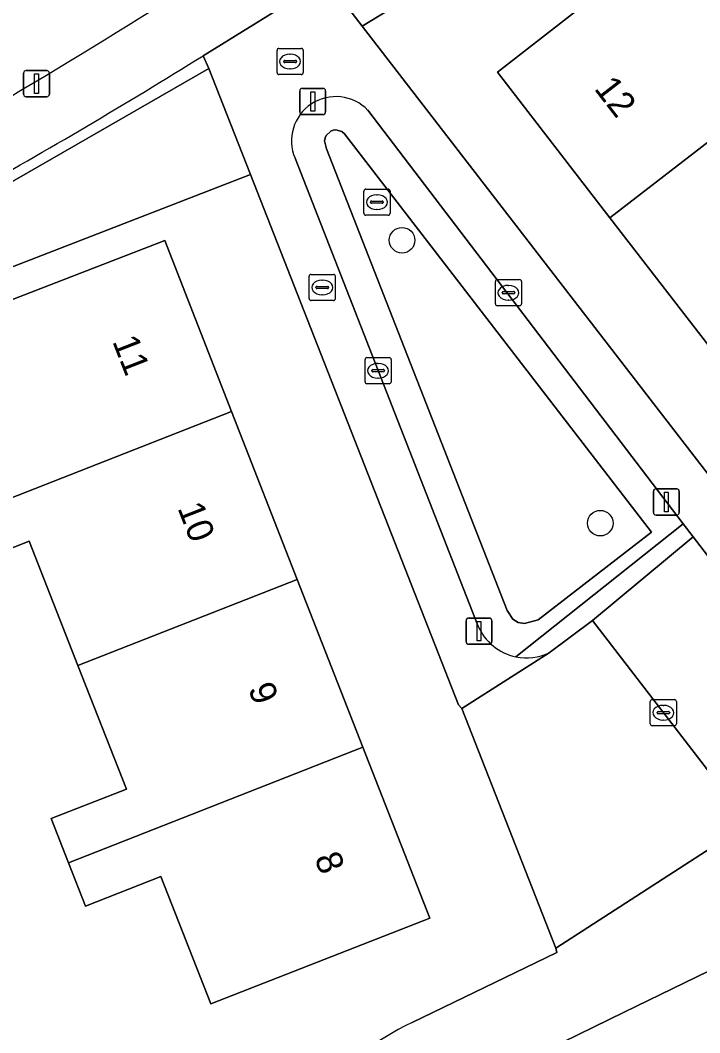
# Model space of a CAD drawing. Extents: x 162661 to 163484, y 380247 to 381230.
# Drawn here: x 163145.52 to 163171.51, y 381014.16 to 381052.89 of the extents above; entities that cross this region are included whole.
import ezdxf

# ---------------------------------------------------------------- set-up
doc = ezdxf.new("R2010")
doc.units = 0
for name, color, linetype in [('IMGEO_Boom', 7, 'Continuous'), ('IMGEO_Brandkraan', 7, 'Continuous'), ('IMGEO_Erf', 7, 'Continuous'), ('IMGEO_Groenvoorziening', 7, 'Continuous'), ('IMGEO_Kolk', 7, 'Continuous'), ('IMGEO_Lichtmast', 7, 'Continuous'), ('IMGEO_Loofbos', 7, 'Continuous'), ('IMGEO_Pand', 7, 'Continuous'), ('IMGEO_Pand_nummerreeks', 7, 'Continuous'), ('IMGEO_Parkeervlak_open', 7, 'Continuous'), ('IMGEO_Rijbaan_lokaal_open', 7, 'Continuous'), ('IMGEO_Rioolput', 7, 'Continuous'), ('IMGEO_Voetpad_open', 7, 'Continuous')]:
    doc.layers.add(name, color=color, linetype=linetype)

msp = doc.modelspace()

# ---------------------------------------------------------------- linework, layer by layer
at = {"layer": 'IMGEO_Boom'}
for centre in [(163160.123, 381044.477), (163167.702, 381033.654)]:
    msp.add_circle(centre, 0.489, dxfattribs=at)
at = {"layer": 'IMGEO_Brandkraan'}
for p, q in [((163156.57, 381042.245), (163156.57, 381043.097)), ((163156.645, 381043.171), (163157.497, 381043.171)), ((163157.571, 381043.097), (163157.571, 381042.245)), ((163156.872, 381042.714), (163157.27, 381042.714)), ((163157.058, 381042.951), (163157.083, 381042.951)), ((163156.829, 381042.665), (163156.829, 381042.677)), ((163157.267, 381042.628), (163156.869, 381042.628)), ((163157.081, 381042.391), (163157.056, 381042.391)), ((163157.313, 381042.677), (163157.313, 381042.665)), ((163157.497, 381042.171), (163156.645, 381042.171))]:
    msp.add_line(p, q, dxfattribs=at)
for points in [[(163156.57, 381042.245), (163156.57, 381043.097)], [(163156.645, 381043.171), (163157.497, 381043.171)], [(163157.571, 381043.097), (163157.571, 381042.245)], [(163157.497, 381042.171), (163156.645, 381042.171)]]:
    msp.add_lwpolyline(points, dxfattribs=at)
for centre, radius, start, end in [((163156.647, 381043.095), 0.0765, 91.552, 178.448), ((163156.647, 381043.095), 0.0765, 91.552, 178.448), ((163157.495, 381043.095), 0.0765, 1.552, 88.448), ((163157.495, 381043.095), 0.0765, 1.552, 88.448), ((163156.869, 381042.674), 0.0403, 85.8775, 175.7526), ((163157.274, 381042.676), 0.0386, 1.7309, 96.639), ((163156.866, 381042.664), 0.0366, 178.938, 274.7102), ((163157.27, 381042.671), 0.043, 264.8664, 352.4533), ((163156.647, 381042.247), 0.0765, 181.552, 268.448), ((163156.647, 381042.247), 0.0765, 181.552, 268.448), ((163157.495, 381042.247), 0.0765, 271.552, 358.448), ((163157.495, 381042.247), 0.0765, 271.552, 358.448)]:
    msp.add_arc(centre, radius, start, end, dxfattribs=at)
for centre, major_axis, ratio, start_param, end_param in [((163157.057, 381042.671), (-0.387, 0.002), 0.722429, 4.712389, 7.853982), ((163157.082, 381042.671), (-0.39, 0.002), 0.717154, 1.570796, 4.712389)]:
    msp.add_ellipse(centre, major_axis=major_axis, ratio=ratio, start_param=start_param, end_param=end_param, dxfattribs=at)
at = {"layer": 'IMGEO_Erf'}
for points in [[(163183.983, 381058.045), (163198.909, 381037.268), (163207.172, 381043.323), (163215.696, 381049.583), (163215.608, 381049.723), (163210.472, 381058.155), (163197.39, 381079.623), (163187.607, 381072.029), (163175.603, 381063.541), (163168.423, 381058.662), (163158.593, 381052.674), (163180.067, 381024.856)], [(163162.414, 381026.565), (163162.279, 381026.698), (163154.328, 381046.987), (163144.896, 381043.328), (163143.928, 381045.981), (163137.766, 381042.44), (163133.585, 381040.037), (163133.484, 381038.184), (163132.855, 381030.173), (163133.892, 381030.091), (163132.494, 381012.197), (163152.72, 381007.872), (163152.681, 381007.77), (163154.245, 381007.436), (163154.323, 381007.677)], [(163160.511, 381014.551), (163166.037, 381017.229), (163166.001, 381017.389), (163162.414, 381026.565)]]:
    msp.add_lwpolyline(points, dxfattribs=at)
for points in [[(163174.064, 381052.219), (163176.518, 381054.118), (163177.61, 381052.709), (163178.706, 381051.294), (163176.245, 381049.39), (163179.376, 381045.345), (163182.493, 381041.318), (163184.948, 381043.218), (163186.063, 381041.778), (163187.153, 381040.369), (163184.694, 381038.464), (163187.904, 381034.319), (163184.319, 381031.553), (163185.906, 381029.496), (163182.75, 381027.061), (163181.163, 381029.118), (163180.804, 381028.841), (163176.51, 381034.403), (163172.286, 381039.873), (163168.065, 381045.341), (163163.768, 381050.906), (163170.824, 381056.405)], [(163147.725, 381028.21), (163145.86, 381032.964), (163142.978, 381031.833), (163142.322, 381033.501), (163141.663, 381035.179), (163144.544, 381036.31), (163142.625, 381041.199), (163145.295, 381042.235), (163151.049, 381044.467), (163153.604, 381037.927), (163156.115, 381031.501), (163158.624, 381025.077), (163161.179, 381018.538), (163152.811, 381015.257), (163150.896, 381020.137), (163148.014, 381019.006), (163147.364, 381020.659), (163146.699, 381022.352), (163149.58, 381023.482)]]:
    msp.add_lwpolyline(points, close=True, dxfattribs=at)
msp.add_arc((163165.964, 381003.42), 12.395, 116.0996, 159.913, dxfattribs=at)
at = {"layer": 'IMGEO_Groenvoorziening'}
for points in [[(163157.958, 381053.496), (163158.593, 381052.674), (163168.423, 381058.662), (163175.603, 381063.541), (163187.607, 381072.029), (163197.39, 381079.623), (163196.99, 381080.281), (163177.8, 381066.44)], [(163154.328, 381046.987), (163153.268, 381049.69), (163152.737, 381051.044), (163143.928, 381045.981), (163144.896, 381043.328)], [(163164.8, 381029.811), (163165.325, 381029.957), (163169.666, 381033.313), (163157.928, 381048.553), (163157.821, 381048.635), (163157.59, 381048.703), (163157.489, 381048.695), (163157.395, 381048.655), (163157.22, 381048.488), (163157.177, 381048.397), (163157.162, 381048.281), (163157.228, 381047.979), (163164.143, 381030.309), (163164.353, 381029.985), (163164.561, 381029.85)], [(163157.228, 381047.979), (163157.162, 381048.281), (163157.177, 381048.397), (163157.22, 381048.488), (163157.395, 381048.655), (163157.489, 381048.695), (163157.59, 381048.703), (163157.821, 381048.635), (163157.928, 381048.553), (163169.666, 381033.313), (163165.325, 381029.957), (163164.8, 381029.811), (163164.561, 381029.85), (163164.353, 381029.985), (163164.143, 381030.309)]]:
    msp.add_lwpolyline(points, close=True, dxfattribs=at)
for points in [[(163152.737, 381051.044), (163152.52, 381051.539)], [(163137.038, 381042.612), (163137.766, 381042.44), (163143.928, 381045.981), (163152.737, 381051.044)], [(163164.477, 381028.541), (163170.874, 381033.624), (163158.817, 381049.448)], [(163156.029, 381047.613), (163163.024, 381029.737)]]:
    msp.add_lwpolyline(points, dxfattribs=at)
for centre, radius, start, end in [((163030.104, 381248.524), 231.924, 299.2798, 301.85889), ((163157.591, 381048.276), 1.696, 43.7034, 203.0007), ((163164.885, 381030.518), 2.019, 202.7562, 258.3266)]:
    msp.add_arc(centre, radius, start, end, dxfattribs=at)
at = {"layer": 'IMGEO_Kolk'}
for p, q in [((163155.341, 381050.891), (163155.341, 381051.743)), ((163155.416, 381051.817), (163156.268, 381051.817)), ((163156.342, 381051.743), (163156.342, 381050.891)), ((163155.6, 381051.311), (163155.6, 381051.323)), ((163156.038, 381051.274), (163155.64, 381051.274)), ((163155.643, 381051.36), (163156.041, 381051.36)), ((163155.829, 381051.597), (163155.854, 381051.597)), ((163156.084, 381051.323), (163156.084, 381051.311)), ((163155.852, 381051.037), (163155.827, 381051.037)), ((163156.268, 381050.817), (163155.416, 381050.817)), ((163163.691, 381042.044), (163163.691, 381042.896)), ((163163.766, 381042.97), (163164.618, 381042.97)), ((163164.179, 381042.75), (163164.204, 381042.75)), ((163164.692, 381042.896), (163164.692, 381042.044)), ((163163.95, 381042.464), (163163.95, 381042.476)), ((163164.388, 381042.427), (163163.99, 381042.427)), ((163163.993, 381042.513), (163164.391, 381042.513)), ((163164.434, 381042.476), (163164.434, 381042.464)), ((163164.618, 381041.97), (163163.766, 381041.97)), ((163164.202, 381042.19), (163164.177, 381042.19)), ((163158.706, 381039.06), (163158.706, 381039.912)), ((163158.781, 381039.986), (163159.633, 381039.986)), ((163159.194, 381039.766), (163159.219, 381039.766)), ((163159.707, 381039.912), (163159.707, 381039.06)), ((163158.965, 381039.48), (163158.965, 381039.492)), ((163159.403, 381039.443), (163159.005, 381039.443)), ((163159.008, 381039.529), (163159.406, 381039.529)), ((163159.449, 381039.492), (163159.449, 381039.48)), ((163159.633, 381038.986), (163158.781, 381038.986)), ((163159.217, 381039.206), (163159.192, 381039.206)), ((163169.614, 381025.976), (163169.614, 381026.828)), ((163169.689, 381026.902), (163170.541, 381026.902)), ((163170.615, 381026.828), (163170.615, 381025.976)), ((163169.916, 381026.445), (163170.314, 381026.445)), ((163170.102, 381026.682), (163170.127, 381026.682)), ((163169.873, 381026.396), (163169.873, 381026.408)), ((163170.311, 381026.359), (163169.913, 381026.359)), ((163170.125, 381026.122), (163170.1, 381026.122)), ((163170.357, 381026.408), (163170.357, 381026.396)), ((163170.541, 381025.902), (163169.689, 381025.902))]:
    msp.add_line(p, q, dxfattribs=at)
for points in [[(163155.341, 381050.891), (163155.341, 381051.743)], [(163155.416, 381051.817), (163156.268, 381051.817)], [(163156.342, 381051.743), (163156.342, 381050.891)], [(163156.268, 381050.817), (163155.416, 381050.817)], [(163163.691, 381042.044), (163163.691, 381042.896)], [(163163.766, 381042.97), (163164.618, 381042.97)], [(163164.692, 381042.896), (163164.692, 381042.044)], [(163164.618, 381041.97), (163163.766, 381041.97)], [(163158.706, 381039.06), (163158.706, 381039.912)], [(163158.781, 381039.986), (163159.633, 381039.986)], [(163159.707, 381039.912), (163159.707, 381039.06)], [(163159.633, 381038.986), (163158.781, 381038.986)], [(163169.614, 381025.976), (163169.614, 381026.828)], [(163169.689, 381026.902), (163170.541, 381026.902)], [(163170.615, 381026.828), (163170.615, 381025.976)], [(163170.541, 381025.902), (163169.689, 381025.902)]]:
    msp.add_lwpolyline(points, dxfattribs=at)
for centre, radius, start, end in [((163155.418, 381051.741), 0.0765, 91.552, 178.448), ((163155.418, 381051.741), 0.0765, 91.552, 178.448), ((163156.266, 381051.741), 0.0765, 1.552, 88.448), ((163156.266, 381051.741), 0.0765, 1.552, 88.448), ((163155.64, 381051.32), 0.0403, 85.8775, 175.7526), ((163155.637, 381051.31), 0.0366, 178.938, 274.7102), ((163156.041, 381051.317), 0.043, 264.8664, 352.4533), ((163156.045, 381051.322), 0.0386, 1.7309, 96.639), ((163155.418, 381050.893), 0.0765, 181.552, 268.448), ((163155.418, 381050.893), 0.0765, 181.552, 268.448), ((163156.266, 381050.893), 0.0765, 271.552, 358.448), ((163156.266, 381050.893), 0.0765, 271.552, 358.448), ((163163.768, 381042.894), 0.0765, 91.552, 178.448), ((163163.768, 381042.894), 0.0765, 91.552, 178.448), ((163164.616, 381042.894), 0.0765, 1.552, 88.448), ((163164.616, 381042.894), 0.0765, 1.552, 88.448), ((163163.99, 381042.473), 0.0403, 85.8775, 175.7526), ((163163.987, 381042.463), 0.0366, 178.938, 274.7102), ((163164.391, 381042.47), 0.043, 264.8664, 352.4533), ((163164.395, 381042.475), 0.0386, 1.7309, 96.639), ((163163.768, 381042.046), 0.0765, 181.552, 268.448), ((163163.768, 381042.046), 0.0765, 181.552, 268.448), ((163164.616, 381042.046), 0.0765, 271.552, 358.448), ((163164.616, 381042.046), 0.0765, 271.552, 358.448), ((163158.783, 381039.91), 0.0765, 91.552, 178.448), ((163158.783, 381039.91), 0.0765, 91.552, 178.448), ((163159.631, 381039.91), 0.0765, 1.552, 88.448), ((163159.631, 381039.91), 0.0765, 1.552, 88.448), ((163159.005, 381039.489), 0.0403, 85.8775, 175.7526), ((163159.002, 381039.479), 0.0366, 178.938, 274.7102), ((163159.406, 381039.486), 0.043, 264.8664, 352.4533), ((163159.41, 381039.491), 0.0386, 1.7309, 96.639), ((163158.783, 381039.062), 0.0765, 181.552, 268.448), ((163158.783, 381039.062), 0.0765, 181.552, 268.448), ((163159.631, 381039.062), 0.0765, 271.552, 358.448), ((163159.631, 381039.062), 0.0765, 271.552, 358.448), ((163169.691, 381026.826), 0.0765, 91.552, 178.448), ((163169.691, 381026.826), 0.0765, 91.552, 178.448), ((163170.539, 381026.826), 0.0765, 1.552, 88.448), ((163170.539, 381026.826), 0.0765, 1.552, 88.448), ((163169.913, 381026.405), 0.0403, 85.8775, 175.7526), ((163170.318, 381026.407), 0.0386, 1.7309, 96.639), ((163169.91, 381026.395), 0.0366, 178.938, 274.7102), ((163170.314, 381026.402), 0.043, 264.8664, 352.4533), ((163169.691, 381025.978), 0.0765, 181.552, 268.448), ((163169.691, 381025.978), 0.0765, 181.552, 268.448), ((163170.539, 381025.978), 0.0765, 271.552, 358.448), ((163170.539, 381025.978), 0.0765, 271.552, 358.448)]:
    msp.add_arc(centre, radius, start, end, dxfattribs=at)
for centre, major_axis, ratio, start_param, end_param in [((163155.828, 381051.317), (-0.387, 0.002), 0.722429, 4.712389, 7.853982), ((163155.853, 381051.317), (-0.39, 0.002), 0.717154, 1.570796, 4.712389), ((163164.178, 381042.47), (-0.387, 0.002), 0.722429, 4.712389, 7.853982), ((163164.203, 381042.47), (-0.39, 0.002), 0.717154, 1.570796, 4.712389), ((163159.193, 381039.486), (-0.387, 0.002), 0.722429, 4.712389, 7.853982), ((163159.218, 381039.486), (-0.39, 0.002), 0.717154, 1.570796, 4.712389), ((163170.101, 381026.402), (-0.387, 0.002), 0.722429, 4.712389, 7.853982), ((163170.126, 381026.402), (-0.39, 0.002), 0.717154, 1.570796, 4.712389)]:
    msp.add_ellipse(centre, major_axis=major_axis, ratio=ratio, start_param=start_param, end_param=end_param, dxfattribs=at)
at = {"layer": 'IMGEO_Lichtmast'}
for p, q in [((163145.646, 381050.069), (163145.646, 381050.869)), ((163145.646, 381050.869), (163145.646, 381050.069)), ((163145.746, 381050.969), (163146.536, 381050.969)), ((163146.536, 381050.969), (163145.746, 381050.969)), ((163146.636, 381050.869), (163146.636, 381050.069)), ((163146.636, 381050.069), (163146.636, 381050.869)), ((163156.211, 381049.387), (163156.211, 381050.187)), ((163156.211, 381050.187), (163156.211, 381049.387)), ((163156.311, 381050.287), (163157.101, 381050.287)), ((163157.101, 381050.287), (163156.311, 381050.287)), ((163157.201, 381050.187), (163157.201, 381049.387)), ((163157.201, 381049.387), (163157.201, 381050.187)), ((163146.536, 381049.969), (163145.746, 381049.969)), ((163145.746, 381049.969), (163146.536, 381049.969)), ((163157.101, 381049.287), (163156.311, 381049.287)), ((163156.311, 381049.287), (163157.101, 381049.287)), ((163169.835, 381034.965), (163170.625, 381034.965)), ((163170.625, 381034.965), (163169.835, 381034.965)), ((163169.735, 381034.065), (163169.735, 381034.865)), ((163169.735, 381034.865), (163169.735, 381034.065)), ((163170.725, 381034.865), (163170.725, 381034.065)), ((163170.725, 381034.065), (163170.725, 381034.865)), ((163170.625, 381033.965), (163169.835, 381033.965)), ((163169.835, 381033.965), (163170.625, 381033.965)), ((163162.571, 381029.122), (163162.571, 381029.922)), ((163162.571, 381029.922), (163162.571, 381029.122)), ((163162.671, 381030.022), (163163.461, 381030.022)), ((163163.461, 381030.022), (163162.671, 381030.022)), ((163163.561, 381029.922), (163163.561, 381029.122)), ((163163.561, 381029.122), (163163.561, 381029.922)), ((163163.461, 381029.022), (163162.671, 381029.022)), ((163162.671, 381029.022), (163163.461, 381029.022))]:
    msp.add_line(p, q, dxfattribs=at)
for points in [[(163146.066, 381050.844), (163146.216, 381050.844), (163146.216, 381050.094), (163146.066, 381050.094), (163146.066, 381050.844)], [(163156.631, 381050.162), (163156.781, 381050.162), (163156.781, 381049.412), (163156.631, 381049.412), (163156.631, 381050.162)], [(163170.155, 381034.84), (163170.305, 381034.84), (163170.305, 381034.09), (163170.155, 381034.09), (163170.155, 381034.84)], [(163162.991, 381029.897), (163163.141, 381029.897), (163163.141, 381029.147), (163162.991, 381029.147), (163162.991, 381029.897)]]:
    msp.add_lwpolyline(points, dxfattribs=at)
for centre, start, end in [((163145.746, 381050.869), 90, 180), ((163145.746, 381050.869), 90, 180), ((163146.536, 381050.869), 0, 90), ((163146.536, 381050.869), 360, 90), ((163145.746, 381050.069), 180, 270), ((163145.746, 381050.069), 180, 270), ((163146.536, 381050.069), 270, 0), ((163146.536, 381050.069), 270, 0), ((163156.311, 381050.187), 90, 180), ((163156.311, 381050.187), 90, 180), ((163157.101, 381050.187), 0, 90), ((163157.101, 381050.187), 360, 90), ((163156.311, 381049.387), 180, 270), ((163156.311, 381049.387), 180, 270), ((163157.101, 381049.387), 270, 0), ((163157.101, 381049.387), 270, 0), ((163169.835, 381034.865), 90, 180), ((163169.835, 381034.865), 90, 180), ((163170.625, 381034.865), 0, 90), ((163170.625, 381034.865), 360, 90), ((163169.835, 381034.065), 180, 270), ((163169.835, 381034.065), 180, 270), ((163170.625, 381034.065), 270, 0), ((163170.625, 381034.065), 270, 0), ((163162.671, 381029.922), 90, 180), ((163162.671, 381029.922), 90, 180), ((163163.461, 381029.922), 0, 90), ((163163.461, 381029.922), 360, 90), ((163162.671, 381029.122), 180, 270), ((163162.671, 381029.122), 180, 270), ((163163.461, 381029.122), 270, 0), ((163163.461, 381029.122), 270, 0)]:
    msp.add_arc(centre, 0.1, start, end, dxfattribs=at)
at = {"layer": 'IMGEO_Loofbos'}
msp.add_arc((163001.958, 381290.973), 280.328, 298.74373, 302.22792, dxfattribs=at)
at = {"layer": 'IMGEO_Pand'}
for points in [[(163168.065, 381045.341), (163177.61, 381052.709), (163176.518, 381054.118), (163174.064, 381052.219), (163170.824, 381056.405), (163163.768, 381050.906)], [(163168.065, 381045.341), (163172.286, 381039.873), (163179.376, 381045.345), (163176.245, 381049.39), (163178.706, 381051.294), (163177.61, 381052.709)], [(163151.049, 381044.467), (163145.295, 381042.235), (163142.625, 381041.199), (163144.544, 381036.31), (163141.663, 381035.179), (163142.322, 381033.501), (163153.604, 381037.927)], [(163156.115, 381031.501), (163153.604, 381037.927), (163142.322, 381033.501), (163142.978, 381031.833), (163145.86, 381032.964), (163147.725, 381028.21)], [(163156.115, 381031.501), (163147.725, 381028.21), (163149.58, 381023.482), (163146.699, 381022.352), (163147.364, 381020.659), (163158.624, 381025.077)], [(163147.364, 381020.659), (163148.014, 381019.006), (163150.896, 381020.137), (163152.811, 381015.257), (163161.179, 381018.538), (163158.624, 381025.077)]]:
    msp.add_lwpolyline(points, close=True, dxfattribs=at)
at = {"layer": 'IMGEO_Parkeervlak_open'}
msp.add_lwpolyline([(163171.249, 381033.131), (163167.405, 381029.923), (163173.381, 381022.158), (163177.329, 381025.209)], close=True, dxfattribs=at)
at = {"layer": 'IMGEO_Rijbaan_lokaal_open'}
msp.add_lwpolyline([(163167.405, 381029.923), (163165.749, 381028.692), (163162.414, 381026.565), (163166.001, 381017.389), (163173.381, 381022.158)], close=True, dxfattribs=at)
msp.add_lwpolyline([(163173.628, 381017.387), (163173.232, 381017.195), (163168.614, 381014.939), (163162.774, 381012.085)], dxfattribs=at)
at = {"layer": 'IMGEO_Rioolput'}
for p, q in [((163158.661, 381045.508), (163158.661, 381046.36)), ((163158.736, 381046.434), (163159.588, 381046.434)), ((163159.149, 381046.214), (163159.174, 381046.214)), ((163159.662, 381046.36), (163159.662, 381045.508)), ((163158.92, 381045.928), (163158.92, 381045.94)), ((163159.358, 381045.891), (163158.96, 381045.891)), ((163158.963, 381045.977), (163159.361, 381045.977)), ((163159.404, 381045.94), (163159.404, 381045.928)), ((163159.588, 381045.434), (163158.736, 381045.434)), ((163159.172, 381045.654), (163159.147, 381045.654))]:
    msp.add_line(p, q, dxfattribs=at)
for points in [[(163158.661, 381045.508), (163158.661, 381046.36)], [(163158.736, 381046.434), (163159.588, 381046.434)], [(163159.662, 381046.36), (163159.662, 381045.508)], [(163159.588, 381045.434), (163158.736, 381045.434)]]:
    msp.add_lwpolyline(points, dxfattribs=at)
for centre, radius, start, end in [((163158.738, 381046.358), 0.0765, 91.552, 178.448), ((163158.738, 381046.358), 0.0765, 91.552, 178.448), ((163159.586, 381046.358), 0.0765, 1.552, 88.448), ((163159.586, 381046.358), 0.0765, 1.552, 88.448), ((163158.96, 381045.937), 0.0403, 85.8775, 175.7526), ((163158.957, 381045.927), 0.0366, 178.938, 274.7102), ((163159.361, 381045.934), 0.043, 264.8664, 352.4533), ((163159.365, 381045.939), 0.0386, 1.7309, 96.639), ((163158.738, 381045.51), 0.0765, 181.552, 268.448), ((163158.738, 381045.51), 0.0765, 181.552, 268.448), ((163159.586, 381045.51), 0.0765, 271.552, 358.448), ((163159.586, 381045.51), 0.0765, 271.552, 358.448)]:
    msp.add_arc(centre, radius, start, end, dxfattribs=at)
for centre, major_axis, ratio, start_param, end_param in [((163159.148, 381045.934), (-0.387, 0.002), 0.722429, 4.712389, 7.853982), ((163159.173, 381045.934), (-0.39, 0.002), 0.717154, 1.570796, 4.712389)]:
    msp.add_ellipse(centre, major_axis=major_axis, ratio=ratio, start_param=start_param, end_param=end_param, dxfattribs=at)
at = {"layer": 'IMGEO_Voetpad_open'}
for points in [[(163152.52, 381051.539), (163157.199, 381054.441), (163164.797, 381059.191)], [(163158.593, 381052.674), (163157.958, 381053.496), (163157.199, 381054.441), (163152.52, 381051.539), (163152.737, 381051.044), (163153.268, 381049.69), (163154.328, 381046.987), (163162.279, 381026.698), (163162.414, 381026.565), (163165.749, 381028.692)], [(163158.817, 381049.448), (163170.874, 381033.624), (163171.249, 381033.131), (163177.329, 381025.209), (163180.067, 381024.856), (163158.593, 381052.674)], [(163163.024, 381029.737), (163156.029, 381047.613)], [(163171.249, 381033.131), (163170.874, 381033.624), (163164.477, 381028.541)], [(163165.749, 381028.692), (163167.405, 381029.923), (163171.249, 381033.131)], [(163180.067, 381024.856), (163177.329, 381025.209), (163173.381, 381022.158), (163166.001, 381017.389), (163166.037, 381017.229), (163160.511, 381014.551)], [(163162.774, 381012.085), (163168.614, 381014.939), (163173.232, 381017.195), (163173.628, 381017.387)]]:
    msp.add_lwpolyline(points, dxfattribs=at)
for centre, radius, start, end in [((163001.958, 381290.973), 280.328, 298.74373, 302.22792), ((163030.104, 381248.524), 231.924, 299.2798, 301.85889), ((163157.591, 381048.276), 1.696, 43.7034, 203.0007), ((163164.885, 381030.518), 2.019, 202.7562, 258.3266), ((163164.887, 381030.519), 2.021, 258.2897, 295.2502), ((163164.887, 381030.519), 2.021, 258.2897, 295.2502), ((163165.964, 381003.42), 12.395, 116.0996, 159.913)]:
    msp.add_arc(centre, radius, start, end, dxfattribs=at)

# ---------------------------------------------------------------- texts
at = {"layer": 'IMGEO_Pand_nummerreeks'}
for s, rotation, p in [('12', 307.6711, (163167.441, 381050.272)), ('11', 291.3425, (163149.034, 381040.611)), ('10', 291.3397, (163151.527, 381034.232)), ('9', 291.3397, (163154.225, 381027.325)), ('8', 291.3397, (163156.759, 381020.839))]:
    msp.add_text(s, height=1, rotation=rotation, dxfattribs=at).set_placement(p)

doc.saveas('drawing.dxf')
